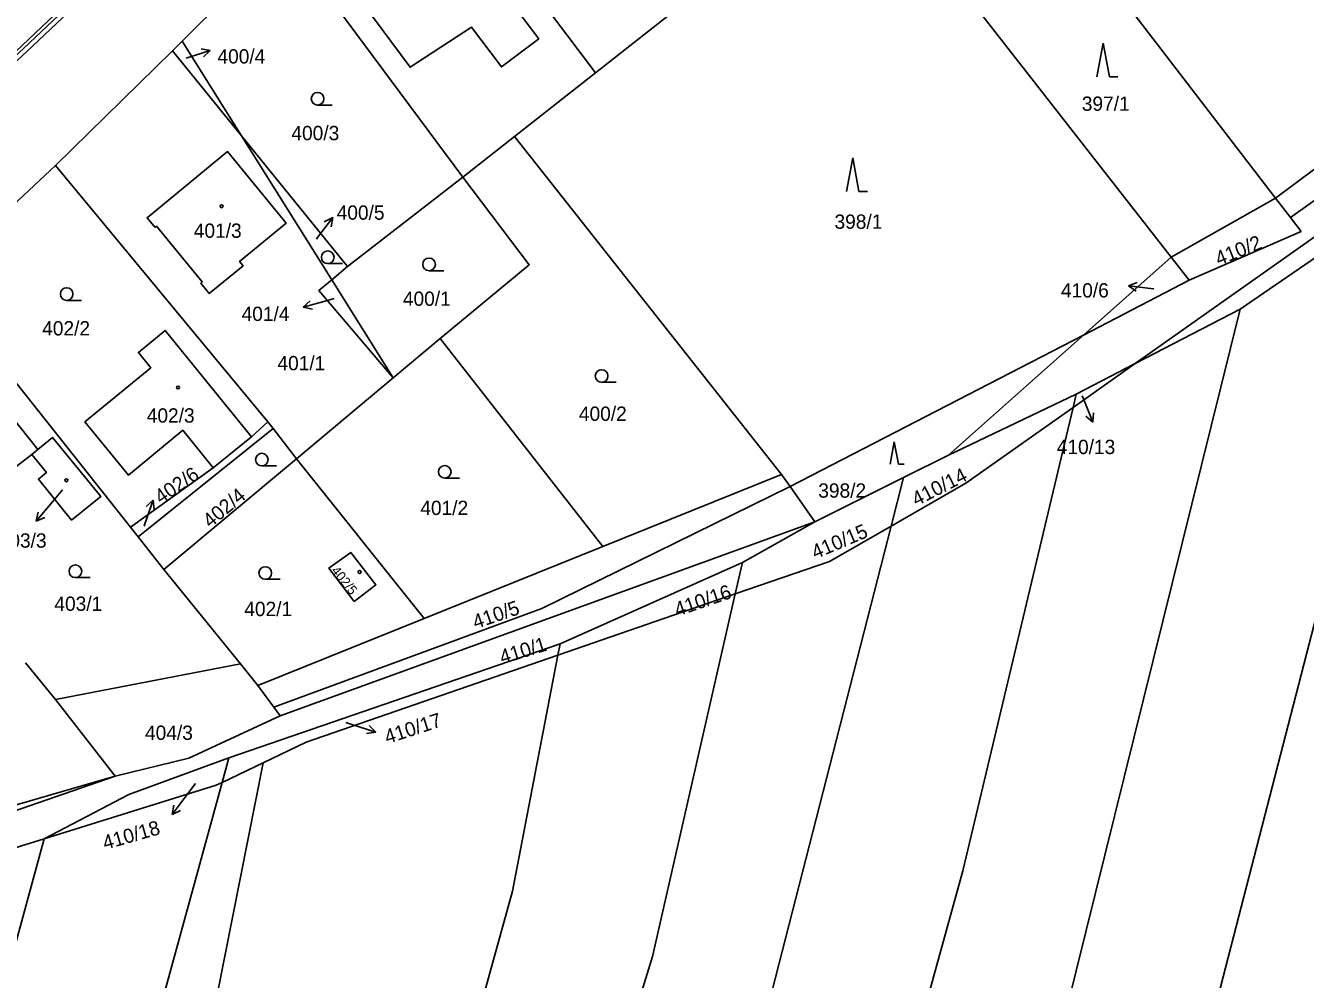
# Model space of a CAD drawing. Extents: x -757266 to -753360, y -1162585 to -1157740.
# Drawn here: x -754263.6 to -754111.5, y -1160892.7 to -1160779.4 of the extents above; entities that cross this region are included whole.
import ezdxf

# ---------------------------------------------------------------- set-up
doc = ezdxf.new("R2010")
doc.units = 0
for name, color, linetype in [('Hranice parcel', 7, 'Continuous'), ('Parcelní čísla', 7, 'Continuous'), ('Pop  PČ popisy', 7, 'Continuous'), ('Vnitřní kresba', 7, 'Continuous'), ('Věcná břemena k části', 7, 'Continuous'), ('Značky budov', 7, 'Continuous'), ('Značky kultur', 7, 'Continuous')]:
    doc.layers.add(name, color=color, linetype=linetype)

msp = doc.modelspace()

# ---------------------------------------------------------------- linework, layer by layer
at = {"layer": 'Hranice parcel'}
for p, q in [((-754218.58, -1160754.85), (-754195.87, -1160785.01)), ((-754244.98, -1160781.26), (-754232.72, -1160769)), ((-754232.72, -1160769), (-754211.64, -1160797.41)), ((-754139.37, -1160768.21), (-754115.03, -1160799.91)), ((-754131.72, -1160819.55), (-754061.08, -1160769.62)), ((-754274.88, -1160792.04), (-754251.33, -1160769.73)), ((-754195.87, -1160785.01), (-754179.93, -1160772.48)), ((-754127.44, -1160806.9), (-754151.09, -1160776.64)), ((-754115.03, -1160799.91), (-754088.86, -1160780.26)), ((-754246.12, -1160782.4), (-754244.98, -1160781.26)), ((-754244.98, -1160781.26), (-754237.93, -1160792.5)), ((-754260.04, -1160796.01), (-754246.12, -1160782.4)), ((-754237.93, -1160792.5), (-754246.12, -1160782.4)), ((-754113.27, -1160802.19), (-754086.54, -1160783.14)), ((-754205.49, -1160792.58), (-754195.87, -1160785.01)), ((-754237.93, -1160792.5), (-754225.35, -1160808.01)), ((-754227.21, -1160809.59), (-754237.93, -1160792.5)), ((-754211.64, -1160797.41), (-754205.49, -1160792.58)), ((-754173.73, -1160832.73), (-754205.49, -1160792.58)), ((-754274.48, -1160809.55), (-754260.04, -1160796.01)), ((-754260.04, -1160796.01), (-754234.81, -1160826.46)), ((-754211.64, -1160797.41), (-754225.35, -1160808.01)), ((-754115.03, -1160799.91), (-754127.44, -1160806.9)), ((-754098.67, -1160798.96), (-754119.24, -1160813.08)), ((-754113.27, -1160802.19), (-754115.03, -1160799.91)), ((-754111.98, -1160803.87), (-754113.27, -1160802.19)), ((-754125.29, -1160809.66), (-754111.98, -1160803.87)), ((-754137.86, -1160816.16), (-754127.44, -1160806.9)), ((-754127.44, -1160806.9), (-754125.29, -1160809.66)), ((-754225.35, -1160808.01), (-754227.21, -1160809.59)), ((-754274.48, -1160809.55), (-754251.12, -1160839.01)), ((-754227.21, -1160809.59), (-754219.91, -1160821.23)), ((-754137.86, -1160816.16), (-754125.29, -1160809.66)), ((-754119.24, -1160813.08), (-754131.72, -1160819.55)), ((-754219.91, -1160821.23), (-754214.32, -1160816.59)), ((-754214.32, -1160816.59), (-754194.98, -1160841.28)), ((-754172.71, -1160834.18), (-754137.86, -1160816.16)), ((-754153.91, -1160830.42), (-754137.86, -1160816.16)), ((-754139.1, -1160824.77), (-754131.72, -1160819.55)), ((-754131.72, -1160819.55), (-754138.73, -1160823.19)), ((-754231.41, -1160830.87), (-754219.91, -1160821.23)), ((-754138.73, -1160823.19), (-754153.91, -1160830.42)), ((-754138.73, -1160823.19), (-754139.1, -1160824.77)), ((-754234.18, -1160827.27), (-754250.23, -1160840.15)), ((-754236.76, -1160828.27), (-754234.81, -1160826.46)), ((-754234.81, -1160826.46), (-754234.18, -1160827.27)), ((-754234.18, -1160827.27), (-754231.41, -1160830.87)), ((-754241.29, -1160831.94), (-754236.76, -1160828.27)), ((-754262.87, -1160830.36), (-754262.13, -1160829.76)), ((-754159.25, -1160833.1), (-754153.91, -1160830.42)), ((-754251.12, -1160839.01), (-754241.29, -1160831.94)), ((-754231.41, -1160830.87), (-754247.16, -1160844.02)), ((-754231.41, -1160830.87), (-754216.23, -1160849.84)), ((-754194.98, -1160841.28), (-754173.73, -1160832.73)), ((-754173.73, -1160832.73), (-754172.71, -1160834.18)), ((-754169.77, -1160838.37), (-754159.25, -1160833.1)), ((-754159.25, -1160833.1), (-754160.73, -1160838.86)), ((-754172.71, -1160834.18), (-754169.77, -1160838.37)), ((-754251.12, -1160839.01), (-754250.23, -1160840.15)), ((-754178.39, -1160843.18), (-754169.77, -1160838.37)), ((-754250.23, -1160840.15), (-754247.16, -1160844.02)), ((-754216.23, -1160849.84), (-754194.98, -1160841.28)), ((-754247.16, -1160844.02), (-754238.05, -1160855.22)), ((-754200.07, -1160852.84), (-754178.39, -1160843.18)), ((-754178.39, -1160843.18), (-754179.25, -1160846.93)), ((-754200.33, -1160854.21), (-754179.25, -1160846.93)), ((-754236, -1160857.79), (-754216.23, -1160849.84)), ((-754239.43, -1160866.42), (-754200.07, -1160852.84)), ((-754200.07, -1160852.84), (-754200.33, -1160854.21)), ((-754263.6, -1160855.11), (-754260.03, -1160859.48)), ((-754260.03, -1160859.48), (-754238.05, -1160855.22)), ((-754238.05, -1160855.22), (-754236, -1160857.79)), ((-754234.09, -1160860.39), (-754236, -1160857.79)), ((-754260.03, -1160859.48), (-754252.93, -1160868.57)), ((-754239.43, -1160866.42), (-754240.23, -1160869.33)), ((-754240.23, -1160869.33), (-754235.37, -1160867)), ((-754274.91, -1160874.96), (-754252.93, -1160868.57)), ((-754283.62, -1160882.92), (-754261.38, -1160876.02))]:
    msp.add_line(p, q, dxfattribs=at)
for points in [[(-754215.48, -1160770.03), (-754212.53, -1160767.8), (-754202.6, -1160780.95), (-754207.04, -1160784.3), (-754210.59, -1160779.59), (-754217.9, -1160784.34), (-754222.46, -1160778.16), (-754214.07, -1160771.98), (-754215.48, -1160770.03)], [(-754248.21, -1160803.37), (-754249.15, -1160802.22), (-754239.59, -1160794.37), (-754232.62, -1160802.85), (-754238.16, -1160807.43), (-754237.74, -1160807.93), (-754241.76, -1160811.22), (-754242.76, -1160809.99), (-754242.59, -1160809.86), (-754248.04, -1160803.22), (-754248.21, -1160803.37)], [(-754214.32, -1160816.59), (-754203.74, -1160807.82), (-754211.64, -1160797.41)], [(-754098.67, -1160798.96), (-754110.12, -1160849.32), (-754121.88, -1160894.88), (-754143.38, -1160986.5), (-754161.87, -1161066.18)], [(-754219.91, -1160821.23), (-754228.72, -1160810.86), (-754227.21, -1160809.59)], [(-754119.24, -1160813.08), (-754149.07, -1160933.43), (-754164.64, -1160995.63), (-754171.67, -1161021.51), (-754182.05, -1161070.71)], [(-754241.29, -1160831.94), (-754244.92, -1160827.47), (-754251.38, -1160832.8), (-754256.55, -1160826.48), (-754248.69, -1160820.05), (-754250.19, -1160818.22), (-754247.02, -1160815.62), (-754236.76, -1160828.27)], [(-754262.87, -1160830.36), (-754266.28, -1160833.03), (-754269.46, -1160829.02), (-754272.04, -1160831.09), (-754278.32, -1160823.16), (-754276.88, -1160822.03), (-754277.64, -1160821.05), (-754277.1, -1160819.34), (-754275.49, -1160818.1), (-754273.69, -1160817.91), (-754272.91, -1160818.9), (-754271.56, -1160817.84), (-754265.33, -1160825.71), (-754262.13, -1160829.76)], [(-754139.1, -1160824.77), (-754152.21, -1160879.84), (-754173.83, -1160958.14), (-754179.85, -1160982.04), (-754181.1, -1160989.94), (-754185.26, -1161004.29), (-754198.56, -1161061.46), (-754200.1, -1161068.14)], [(-754160.73, -1160838.86), (-754151.86, -1160833.78), (-754139.1, -1160824.77)], [(-754262.13, -1160829.76), (-754260.39, -1160828.34), (-754256.93, -1160832.55), (-754254.64, -1160835.33), (-754258.12, -1160838.15), (-754262.07, -1160833.27), (-754261.11, -1160832.5), (-754262.87, -1160830.36)], [(-754172.71, -1160834.18), (-754202.24, -1160848.66), (-754234.09, -1160860.39)], [(-754160.73, -1160838.86), (-754186.23, -1160938.4), (-754200.81, -1160994.66), (-754217.05, -1161065.46)], [(-754179.25, -1160846.93), (-754168.06, -1160843.07), (-754160.73, -1160838.86)], [(-754224.54, -1160847.81), (-754227.55, -1160843.86), (-754224.95, -1160841.99), (-754221.95, -1160845.84), (-754224.54, -1160847.81)], [(-754179.25, -1160846.93), (-754189.1, -1160890.03), (-754200.84, -1160928.27), (-754215.79, -1160985.35), (-754226.68, -1161035.55), (-754233.09, -1161062.92)], [(-754200.33, -1160854.21), (-754205.73, -1160882.26), (-754220.29, -1160934.88), (-754249.41, -1161060.34)], [(-754235.37, -1160867), (-754230.23, -1160864.54), (-754200.33, -1160854.21)], [(-754252.93, -1160868.57), (-754244.19, -1160866.43), (-754233.35, -1160861.4), (-754234.09, -1160860.39)], [(-754249.41, -1161060.34), (-754270.64, -1161056.98), (-754247.49, -1160963.34), (-754249.94, -1160940.51), (-754235.37, -1160867)], [(-754261.38, -1160876.02), (-754251.33, -1160870.76), (-754239.43, -1160866.42)], [(-754240.23, -1160869.33), (-754258.1, -1160934.43), (-754274.18, -1161002.2), (-754288.17, -1161067.13), (-754298.61, -1161110.97), (-754317.3, -1161179.08), (-754343.58, -1161284.28), (-754376.56, -1161413.76)], [(-754252.93, -1160868.57), (-754282.37, -1160878.77), (-754303.7, -1160889.15)], [(-754261.38, -1160876.02), (-754240.94, -1160869.67), (-754240.23, -1160869.33)], [(-754261.38, -1160876.02), (-754273.65, -1160920.93), (-754281.63, -1160958.76), (-754310.59, -1161082.5), (-754337.36, -1161190.1), (-754364.7, -1161299.26), (-754368.3, -1161317.87), (-754385.39, -1161380.66), (-754397.98, -1161421.24)]]:
    msp.add_lwpolyline(points, dxfattribs=at)
at = {"layer": 'Pop  PČ popisy'}
for p, q in [((-754244.51, -1160783.27), (-754244.49, -1160783.26)), ((-754244.49, -1160783.26), (-754241.636, -1160782.333)), ((-754241.636, -1160782.333), (-754242.743, -1160782.166)), ((-754241.636, -1160782.333), (-754242.434, -1160783.118)), ((-754228.89, -1160804.59), (-754227.084, -1160802.193)), ((-754227.084, -1160802.193), (-754228.087, -1160802.692)), ((-754227.084, -1160802.193), (-754227.287, -1160803.294)), ((-754229.01, -1160804.76), (-754228.89, -1160804.59)), ((-754132.519, -1160810.314), (-754131.464, -1160809.939)), ((-754129.54, -1160810.68), (-754132.519, -1160810.314)), ((-754132.519, -1160810.314), (-754131.586, -1160810.933)), ((-754129.54, -1160810.68), (-754129.51, -1160810.68)), ((-754227.71, -1160812.04), (-754230.595, -1160812.867)), ((-754230.595, -1160812.867), (-754229.77, -1160812.11)), ((-754226.9, -1160811.81), (-754227.71, -1160812.04)), ((-754230.595, -1160812.867), (-754229.494, -1160813.072)), ((-754138.02, -1160823.39), (-754137.87, -1160823.75)), ((-754137.87, -1160823.75), (-754136.746, -1160826.532)), ((-754136.746, -1160826.532), (-754137.585, -1160825.792)), ((-754136.746, -1160826.532), (-754136.657, -1160825.416)), ((-754259.22, -1160834.55), (-754260.41, -1160835.99)), ((-754260.41, -1160835.99), (-754262.339, -1160838.289)), ((-754249.42, -1160838.61), (-754248.443, -1160835.773)), ((-754248.443, -1160835.773), (-754249.242, -1160836.556)), ((-754248.443, -1160835.773), (-754248.296, -1160836.882)), ((-754262.339, -1160838.289), (-754262.079, -1160837.2)), ((-754262.339, -1160838.289), (-754261.312, -1160837.844)), ((-754249.51, -1160838.87), (-754249.42, -1160838.61)), ((-754225.54, -1160862.19), (-754224.81, -1160862.43)), ((-754224.81, -1160862.43), (-754221.956, -1160863.357)), ((-754221.956, -1160863.357), (-754223.063, -1160863.524)), ((-754221.956, -1160863.357), (-754222.754, -1160862.572)), ((-754243.41, -1160869.45), (-754244.37, -1160870.75)), ((-754244.37, -1160870.75), (-754246.176, -1160873.147)), ((-754246.176, -1160873.147), (-754245.973, -1160872.046)), ((-754246.176, -1160873.147), (-754245.173, -1160872.648))]:
    msp.add_line(p, q, dxfattribs=at)
at = {"layer": 'Vnitřní kresba'}
msp.add_line((-754169.77, -1160838.37), (-754233.35, -1160861.4), dxfattribs=at)
at = {"layer": 'Věcná břemena k části'}
msp.add_lwpolyline([(-754276.32, -1160792.74), (-754276, -1160793.11), (-754275.37, -1160793.19), (-754271.3, -1160789.67), (-754263.5, -1160782.49), (-754250.7, -1160770.38), (-754240.83, -1160761.1), (-754229.73, -1160750.55), (-754208.06, -1160729.74), (-754199.34, -1160720.91), (-754199.82, -1160720.18), (-754200.17, -1160720.54), (-754199.96, -1160720.83), (-754208.42, -1160729.38), (-754230.07, -1160750.19), (-754241.17, -1160760.74), (-754250.84, -1160769.83), (-754251.02, -1160769.44), (-754251.61, -1160769.99), (-754251.21, -1160770.17), (-754263.84, -1160782.13), (-754271.62, -1160789.29), (-754275.43, -1160792.56), (-754275.72, -1160792.22)], close=True, dxfattribs=at)
at = {"layer": 'Značky budov'}
for centre in [(-754240.2968, -1160800.8592), (-754245.4668, -1160822.3992), (-754258.7368, -1160833.4192), (-754223.8968, -1160844.3192)]:
    msp.add_circle(centre, 0.175, dxfattribs=at)
at = {"layer": 'Značky kultur'}
for p, q in [((-754135.52, -1160781.47), (-754136.27, -1160785.47)), ((-754134.77, -1160785.47), (-754135.52, -1160781.47)), ((-754134.77, -1160785.47), (-754133.774, -1160785.47)), ((-754228.893, -1160788.84), (-754227.143, -1160788.84)), ((-754165.29, -1160795.11), (-754166.04, -1160799.11)), ((-754164.54, -1160799.11), (-754165.29, -1160795.11)), ((-754164.54, -1160799.11), (-754163.544, -1160799.11)), ((-754227.683, -1160807.67), (-754225.933, -1160807.67)), ((-754215.633, -1160808.52), (-754213.883, -1160808.52)), ((-754258.713, -1160812.04), (-754256.963, -1160812.04)), ((-754195.133, -1160821.78), (-754193.383, -1160821.78)), ((-754160.35, -1160828.84), (-754160.852, -1160831.52)), ((-754159.848, -1160831.52), (-754160.35, -1160828.84)), ((-754235.513, -1160831.72), (-754233.763, -1160831.72)), ((-754159.848, -1160831.52), (-754159.18, -1160831.52)), ((-754213.773, -1160833.17), (-754212.023, -1160833.17)), ((-754257.673, -1160844.98), (-754255.923, -1160844.98)), ((-754235.103, -1160845.19), (-754233.353, -1160845.19))]:
    msp.add_line(p, q, dxfattribs=at)
for centre in [(-754228.8929, -1160788.0898), (-754227.6829, -1160806.9198), (-754215.6329, -1160807.7698), (-754258.7129, -1160811.2898), (-754195.1329, -1160821.0298), (-754235.5129, -1160830.9698), (-754213.7729, -1160832.4198), (-754257.6729, -1160844.2298), (-754235.1029, -1160844.4398)]:
    msp.add_circle(centre, 0.75, dxfattribs=at)

# ---------------------------------------------------------------- texts
at = {"layer": 'Parcelní čísla'}
for s, p in [('400/4', (-754240.79, -1160783.898)), ('397/1', (-754138.058, -1160789.52)), ('400/3', (-754232, -1160793.01)), ('400/5', (-754226.62, -1160802.46)), ('401/3', (-754243.6, -1160804.61)), ('398/1', (-754167.45, -1160803.54)), ('410/6', (-754140.537, -1160811.7)), ('400/1', (-754218.75, -1160812.69)), ('401/4', (-754237.917, -1160814.494)), ('402/2', (-754261.62, -1160816.21)), ('401/1', (-754233.66, -1160820.35)), ('402/3', (-754249.19, -1160826.57)), ('400/2', (-754197.83, -1160826.36)), ('410/13', (-754141.035, -1160830.308)), ('398/2', (-754169.38, -1160835.49)), ('401/2', (-754216.68, -1160837.55)), ('403/3', (-754266.788, -1160841.43)), ('403/1', (-754260.17, -1160848.94)), ('402/1', (-754237.6, -1160849.56)), ('404/3', (-754249.4, -1160864.27))]:
    msp.add_text(s, height=1.7, dxfattribs=at).set_placement(p)
for s, height, rotation, p in [('410/2', 1.7, 21.999997, (-754121.781, -1160807.948)), ('402/6', 1.7, 34, (-754247.524, -1160836.304)), ('410/14', 1.7, 27, (-754157.714, -1160836.537)), ('402/4', 1.7, 40, (-754241.643, -1160839.161)), ('410/15', 1.7, 23, (-754169.737, -1160842.822)), ('402/5', 1.139, 309, (-754227.343, -1160844.19)), ('410/16', 1.7, 19, (-754186.123, -1160849.633)), ('410/5', 1.7, 19, (-754210.113, -1160851.123)), ('410/1', 1.7, 17, (-754206.951, -1160855.292)), ('410/17', 1.7, 18, (-754220.609, -1160864.779)), ('410/18', 1.7, 16, (-754254.154, -1160877.354))]:
    msp.add_text(s, height=height, rotation=rotation, dxfattribs=at).set_placement(p)

doc.saveas('drawing.dxf')
